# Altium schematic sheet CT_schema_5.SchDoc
size 293 x 134 mm
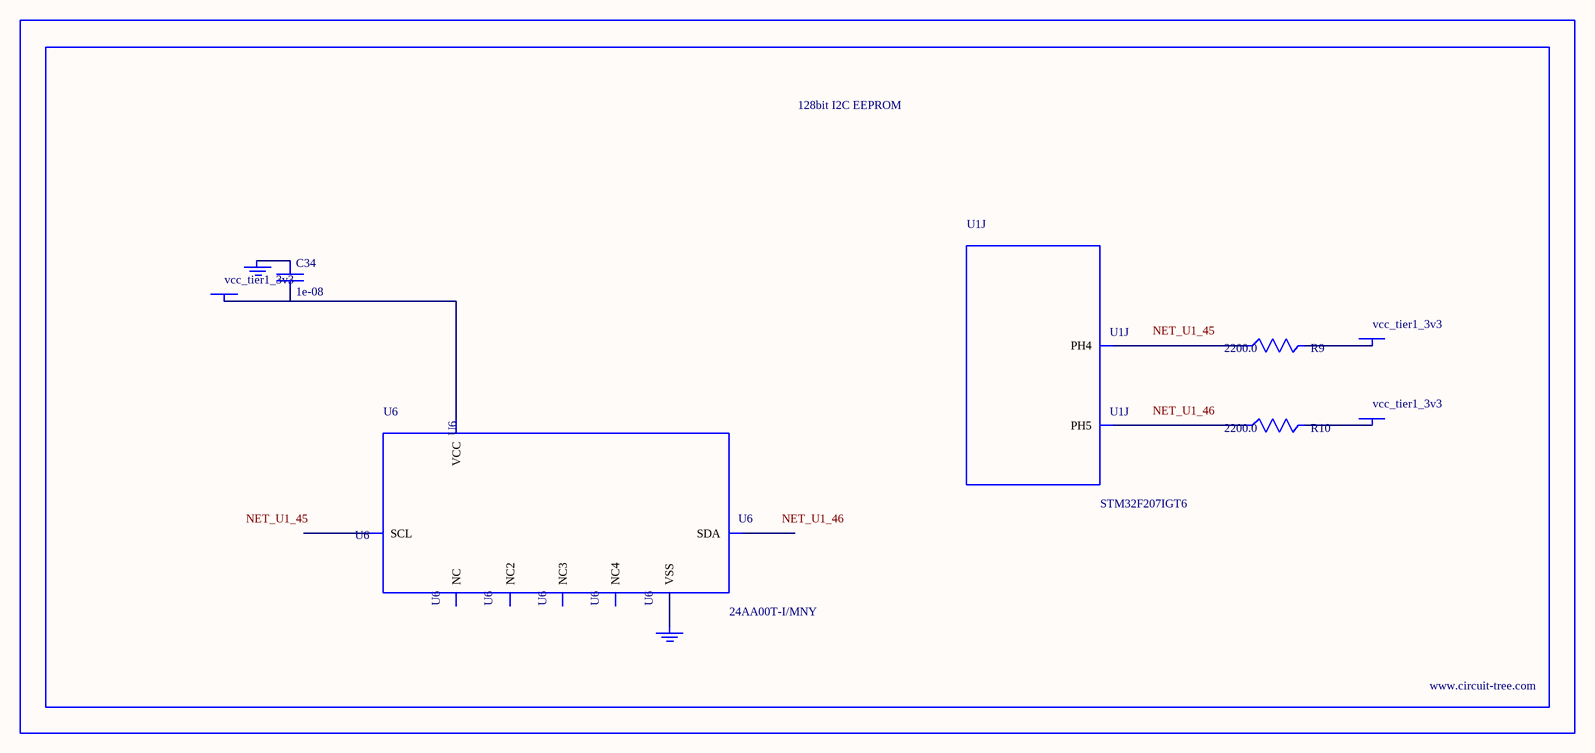
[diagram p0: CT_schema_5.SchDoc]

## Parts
BORDER4  (no value)
C34  1e-08  [C0402]
GND_INSTANCE_4_0  (no value)
GND_INSTANCE_4_1  (no value)
POWER_INSTANCE_4_0  vcc_tier1_3v3
POWER_INSTANCE_4_1  vcc_tier1_3v3
POWER_INSTANCE_4_2  vcc_tier1_3v3
R9  2200.0  [R0603]
R10  2200.0  [R0603]
U1  STM32F207IGT6  [LQFP176]  (part J of 15)
U6  24AA00T-I/MNY  [TDFN-8/6MM]

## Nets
NetC34_1: C34.1 GND_INSTANCE_4_0.0(GND)
NetC34_2: C34.2 POWER_INSTANCE_4_0.0(PWR) U6.8(VCC)
NetGND_INSTANCE_4_1_0: GND_INSTANCE_4_1.0(GND) U6.4(VSS)
NetPOWER_INSTANCE_4_1_0: POWER_INSTANCE_4_1.0(PWR) R9.2
NetPOWER_INSTANCE_4_2_0: POWER_INSTANCE_4_2.0(PWR) R10.2
NetR9_1: R9.1 U1.45(PH4)
NetR10_1: R10.1 U1.46(PH5)

Not connected (* = marked no-connect by the designer): U6 1(NC) 2(NC2) 3(NC3) 5(SDA) 6(SCL) 7(NC4)

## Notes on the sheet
- Labels drawn without touching a wire or pin: NET_U1_45, NET_U1_46

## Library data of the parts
BORDER4 = BORDER_PAGE4
C34 = C0402C103K3RAC
GND_INSTANCE_4_0 GND_INSTANCE_4_1 = GND
POWER_INSTANCE_4_0-POWER_INSTANCE_4_2 = PWR
R9 R10 = RC0603JR-072K2L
